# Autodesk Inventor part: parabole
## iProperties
Created: 2002-09
Part Number: parabole
Material: Par défaut
Document SubType Name: Modélisation
Designer: Maison
Control State: 0
Master: False
Checked Out: False
Shininess: 65.0
Length Units: 11269
Angle Units: 11279
Time Units: 11290
Mass Units: 11283
Length Display Precision: 3
Angle Display Precision: 2
Density: 0.0
Volumn: 0.0
Area: 0.0
PropertySet Name: Model Information
Author: Maison
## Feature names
1. Révolution1 [Revolution]
2. Extrusion1
3. Congé1 [Fillet]
4. Congé2 [Fillet]
5. Extrusion3
6. Révolution2 [Revolution]
7. Extrusion4
